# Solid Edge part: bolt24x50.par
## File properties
Author: jmrobins
Template: Normal.par
Last saved by: mokuno
Revision: 27
Application: Solid Edge
Accuracy: 0.990
Username: jmrobins
文書内容のタイプ: 0
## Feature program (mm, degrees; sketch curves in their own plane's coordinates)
sketch for "unnamed Protrusion 1" plane through (0, 0, 0) normal (1, 0, 0) x-axis (0, 1, 0)
  circle centre (0, 0) radius 12
extrude "unnamed Protrusion 1" add finite 50 along +normal
sketch for "unnamed Protrusion 2" plane through (0, 0, 0) normal (1, 0, 0) x-axis (0, 1, 0)
  line (10.3923, 18) -> (-10.3923, 18)
  line (-10.3923, 18) -> (-20.7846, 0)
  line (-20.7846, 0) -> (-10.3923, -18)
  line (-10.3923, -18) -> (10.3923, -18)
  line (10.3923, -18) -> (20.7846, 0)
  line (20.7846, 0) -> (10.3923, 18)
extrude "unnamed Protrusion 2" add finite 15.9 along -normal
sketch for "unnamed RevolvedCutout 1" plane through (0, 0, 0) normal (0, -1, 0) x-axis (1, 0, 0)
revolve "unnamed RevolvedCutout 1" cut full turn 360 deg
thread "Thread_1"  ThreadDepth = 25 mm
chamfer "Chamfer_1" setback 1.5
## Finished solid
Body 1: solid body, 12 faces, 22 edges, 12 vertices.
  Faces by surface: plane 9, cone 2, cylinder 1
  Edges by curve: line 12, intersection 6, circle 4
Bounding box of the edges (mm): 65.900 x 41.569 x 36.000, from (-15.9, -20.7846, -18) to (50, 20.7846, 18).
Cylindrical faces by radius (mm): R12 x1
Conical faces (half-angle, radius in mm at the cone's reference point): 45 deg R12 x1, 60 deg R18 x1
Planar faces by outward normal: +x 2, +z 1, -x 1, -z 1, oblique 4
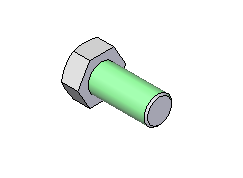
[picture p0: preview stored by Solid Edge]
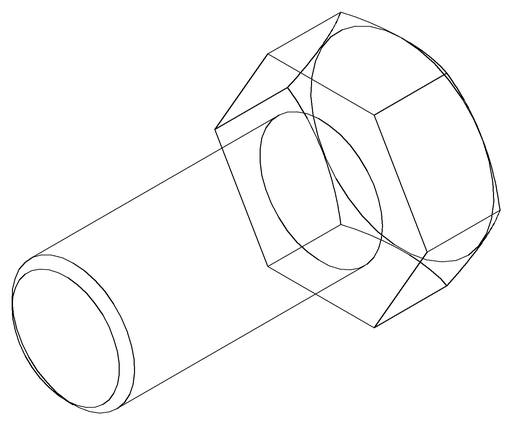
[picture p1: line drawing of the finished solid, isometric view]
